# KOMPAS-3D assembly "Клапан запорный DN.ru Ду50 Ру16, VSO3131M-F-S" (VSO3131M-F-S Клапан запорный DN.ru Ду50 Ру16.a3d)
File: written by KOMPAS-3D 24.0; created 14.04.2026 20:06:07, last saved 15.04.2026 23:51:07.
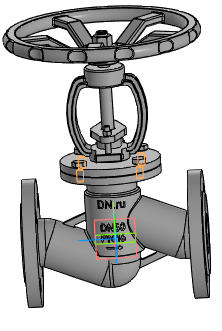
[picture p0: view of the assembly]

Document properties: Автор: R2D2; Полное имя файла: E:\Работа\Зайцев\VSO3131M-F-S Клапан запорный DN.ru Ду15-100 Ру16\DN50\исходные материалы\VSO3131M-F-S Клапан запорный DN.ru Ду50 Ру16.a3d

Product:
- Component [detail]: Корпус  | qty 1  | pos. 1  | Масса: 6.9; Автор: R2D2; source file: Корпус.m3d
- Component [detail]: Клапан запорный DN.ru Ду50 Ру16  | designation VSO1121M-F-S  | qty 1  | pos. 2  | Масса: 14.13; Раздел спецификации: Прочие изделия; Примечание: D090-01947; Автор: R2D2; source file: 2.m3d
- Component [standard]: Hexagon head screw ISO 4017 - М10 x 20  | qty 4  | Масса: 0.023019; Раздел спецификации: Стандартные изделия; Рассекать на разрезах: no
- Part/product: Клапан запорный DN.ru Ду50 Ру16  | designation VSO3131M-F-S
    Масса: 10.5
    Раздел спецификации: Прочие изделия
    Примечание: D090-02951

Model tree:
1. Контекстная связь:1  (with: Ребро.Операция без истории:1, Контекстная связь (Корпус):1)
2. Массив по концентрической сетке:1  (with: Грань.Элемент вращения:2, Грань.Операция без истории:1)  (labels: Грань.Элемент выдавливания:9.Экземпляр ( 1, 2 ))  (4 pattern instances)
     Шаг 2 = 360; Расстояние = -270

Expressions: D090-01947
Referenced files in E:\Работа\Зайцев\VSO3131M-F-S Клапан запорный DN.ru Ду15-100 Ру16\DN50\исходные материалы\: Корпус.m3d, 2.m3d
Referenced files in C:\Program Files\ASCON\KOMPAS-3D v24\Libs\PolynomLib\DATA\vault\Methods\Kompas\3D\: PLib_Bolt_1_ISO_1100.m3d
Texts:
  VSO1121M-F-S
  Hexagon head screw
  BOSimple***PART:c031cb5e-65ec-2f83-1ced-75228c8ad34f***PART:A259_7B16EF33AB1642D2[16;1,5;20;10;-;Undefined]
  Программные изделия  и базы данных
  VSO3131M-F-S
  VSO1121M-F-S Клапан запорный DN.ru Ду50 Ру16
  Hexagon head screw ISO 4017 - М10 x 20 (1)
  hole1
  hole2
  Hexagon head screw ISO 4017 - М10 x 20 (2)
  Hexagon head screw ISO 4017 - М10 x 20 (3)
  Hexagon head screw ISO 4017 - М10 x 20 (4)
  Ось Y.Начало координат
  Плоскость XY.Начало координат
  Плоскость ZX.Начало координат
